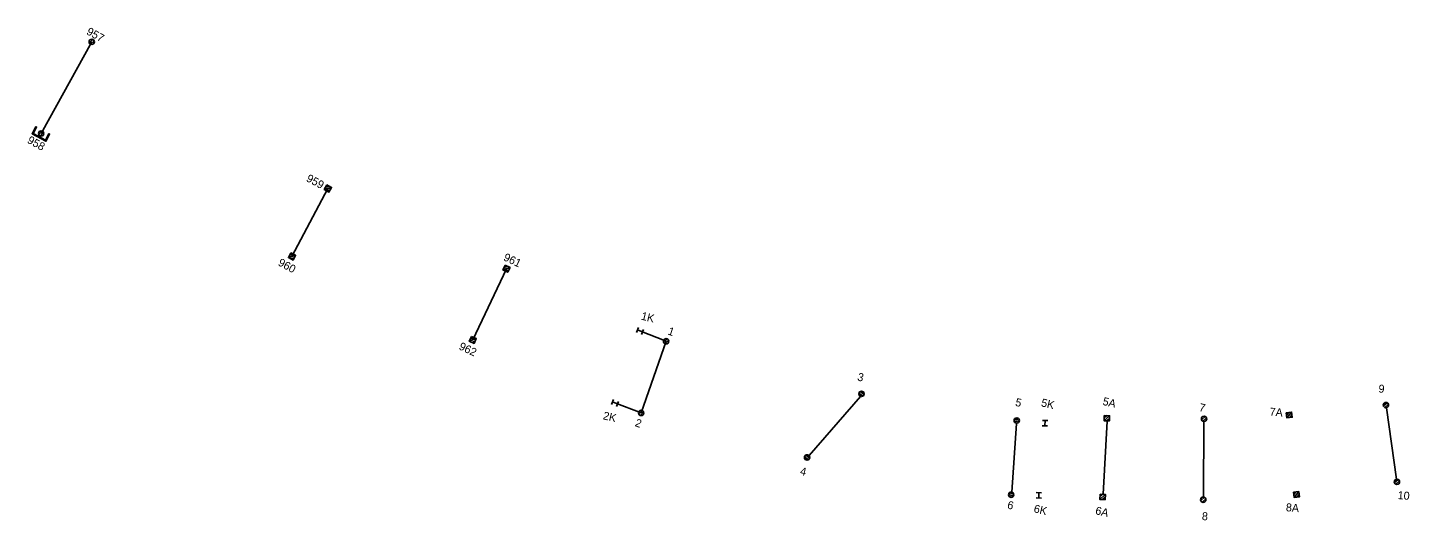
# Model space of a CAD drawing. Extents: x -595867 to -593796, y -1159595 to -1157495.
# Drawn here: x -594055.4 to -593796.4, y -1157836 to -1157743.6 of the extents above; entities that cross this region are included whole.
import ezdxf

# ---------------------------------------------------------------- set-up
doc = ezdxf.new("R2010")
doc.units = 0
doc.layers.add('BVK_kanalizace_jednotna_nova', color=7, linetype='Continuous')
doc.layers.add('Teplarny Horkovod', color=7, linetype='Continuous')

# ---------------------------------------------------------------- blocks, each defined once
blk = doc.blocks.new('C725')
at = {"layer": 'Teplarny Horkovod'}
for p, q in [((-0.46, -0.18), (0.18, 0.46)), ((-0.2, -0.45), (0.45, 0.2))]:
    blk.add_line(p, q, dxfattribs=at)
blk.add_circle((0, 0), 0.5, dxfattribs=at)
blk = doc.blocks.new('C661_3')
at = {"layer": 'Teplarny Horkovod'}
for p, q in [((-0.5, 0.03), (-0.03, 0.5)), ((-0.5, -0.5), (0.5, 0.5)), ((0.03, -0.5), (0.5, -0.03))]:
    blk.add_line(p, q, dxfattribs=at)
blk.add_lwpolyline([(-0.5, 0.5), (0.5, 0.5), (0.5, -0.5), (-0.5, -0.5)], close=True, dxfattribs=at)
blk.add_lwpolyline([(-0.5, 0.5), (0.5, 0.5), (0.5, -0.5), (-0.5, -0.5), (-0.5, 0.5)], dxfattribs=at)
blk = doc.blocks.new('C662')
at = {"layer": 'Teplarny Horkovod'}
for p, q in [((-0.5, 0.5), (0.5, 0.5)), ((0, 0.5), (0, -0.5)), ((-0.5, -0.5), (0.5, -0.5))]:
    blk.add_line(p, q, dxfattribs=at)

msp = doc.modelspace()

# ---------------------------------------------------------------- linework, layer by layer
at = {"layer": 'BVK_kanalizace_jednotna_nova'}
for p, q in [((-593899.56, -1157812.15), (-593898.82, -1157812.71)), ((-593899.33, -1157811.86), (-593898.6, -1157812.41)), ((-593801.25, -1157814.56), (-593800.57, -1157813.95)), ((-593801, -1157814.84), (-593800.32, -1157814.22)), ((-593853.62, -1157817.33), (-593852.58, -1157816.38)), ((-593853.6, -1157816.8), (-593853.11, -1157816.36)), ((-593835.35, -1157817.14), (-593834.67, -1157816.53)), ((-593835.1, -1157817.42), (-593834.42, -1157816.8)), ((-593819.41, -1157816.28), (-593819, -1157815.76)), ((-593819.34, -1157816.81), (-593818.48, -1157815.7)), ((-593818.82, -1157816.75), (-593818.41, -1157816.22)), ((-593870.48, -1157817.2), (-593869.59, -1157816.98)), ((-593870.4, -1157817.56), (-593869.5, -1157817.34)), ((-593865.2, -1157818.26), (-593864.2, -1157818.3)), ((-593865.16, -1157817.26), (-593864.16, -1157817.3)), ((-593864.66, -1157817.28), (-593864.7, -1157818.28)), ((-593853.1, -1157817.36), (-593852.6, -1157816.91)), ((-593909.76, -1157824.08), (-593909.02, -1157824.64)), ((-593909.53, -1157823.79), (-593908.8, -1157824.34)), ((-593799.18, -1157828.95), (-593798.5, -1157828.34)), ((-593798.93, -1157829.23), (-593798.25, -1157828.61)), ((-593871.52, -1157831.14), (-593870.63, -1157830.92)), ((-593871.44, -1157831.5), (-593870.54, -1157831.28)), ((-593866.36, -1157831.81), (-593865.36, -1157831.85)), ((-593866.32, -1157830.81), (-593865.32, -1157830.85)), ((-593865.82, -1157830.83), (-593865.86, -1157831.83)), ((-593854.42, -1157832.09), (-593853.38, -1157831.14)), ((-593854.39, -1157831.56), (-593853.9, -1157831.11)), ((-593853.89, -1157832.11), (-593853.4, -1157831.66)), ((-593835.5, -1157832.31), (-593834.82, -1157831.7)), ((-593835.25, -1157832.59), (-593834.57, -1157831.97)), ((-593818.05, -1157831.2), (-593817.65, -1157830.68)), ((-593817.99, -1157831.73), (-593817.12, -1157830.62)), ((-593817.46, -1157831.67), (-593817.05, -1157831.14))]:
    msp.add_line(p, q, dxfattribs=at)
for points in [[(-593908.89, -1157823.84), (-593899.3, -1157812.78)], [(-593853.58, -1157816.34), (-593852.58, -1157816.39), (-593852.62, -1157817.38), (-593853.62, -1157817.34), (-593853.58, -1157816.34)], [(-593819.47, -1157815.82), (-593818.47, -1157815.7), (-593818.35, -1157816.69), (-593819.34, -1157816.81), (-593819.47, -1157815.82)], [(-593798.77, -1157828.31), (-593800.66, -1157814.94)], [(-593870.91, -1157830.74), (-593870.01, -1157817.83)], [(-593853.78, -1157831.11), (-593853.04, -1157817.41)], [(-593834.98, -1157831.65), (-593834.91, -1157817.37)], [(-593854.37, -1157831.09), (-593853.37, -1157831.14), (-593853.42, -1157832.14), (-593854.42, -1157832.09), (-593854.37, -1157831.09)], [(-593818.11, -1157830.74), (-593817.12, -1157830.61), (-593816.99, -1157831.61), (-593817.99, -1157831.73), (-593818.11, -1157830.74)]]:
    msp.add_lwpolyline(points, dxfattribs=at)
for points in [[(-593853.58, -1157816.34), (-593852.58, -1157816.39), (-593852.62, -1157817.38), (-593853.62, -1157817.34)], [(-593819.47, -1157815.82), (-593818.47, -1157815.7), (-593818.35, -1157816.69), (-593819.34, -1157816.81)], [(-593854.37, -1157831.09), (-593853.37, -1157831.14), (-593853.42, -1157832.14), (-593854.42, -1157832.09)], [(-593818.11, -1157830.74), (-593817.12, -1157830.61), (-593816.99, -1157831.61), (-593817.99, -1157831.73)]]:
    msp.add_lwpolyline(points, close=True, dxfattribs=at)
for centre in [(-593899.08, -1157812.29), (-593899.08, -1157812.29), (-593800.78, -1157814.4), (-593800.78, -1157814.4), (-593869.99, -1157817.28), (-593869.99, -1157817.28), (-593834.88, -1157816.98), (-593834.88, -1157816.98), (-593909.28, -1157824.22), (-593909.28, -1157824.22), (-593798.71, -1157828.79), (-593798.71, -1157828.79), (-593871.03, -1157831.22), (-593871.03, -1157831.22), (-593835.03, -1157832.15), (-593835.03, -1157832.15)]:
    msp.add_circle(centre, 0.5, dxfattribs=at)
at = {"layer": 'Teplarny Horkovod'}
for p, q in [((-594043.38, -1157746.25), (-594052.86, -1157763.45)), ((-593999.1, -1157773.76), (-594005.85, -1157786.51)), ((-593965.62, -1157788.82), (-593971.95, -1157802.18)), ((-593935.71, -1157802.42), (-593940.62, -1157800.49)), ((-593935.71, -1157802.42), (-593940.39, -1157815.87)), ((-593940.39, -1157815.87), (-593945.31, -1157814))]:
    msp.add_line(p, q, dxfattribs=at)
msp.add_lwpolyline([(-594053.87, -1157762.16), (-594054.57, -1157763.49), (-594051.98, -1157764.9), (-594051.27, -1157763.57), (-594051.41, -1157763.49), (-594052.04, -1157764.68), (-594054.35, -1157763.42), (-594053.73, -1157762.23)], close=True, dxfattribs=at)

# ---------------------------------------------------------------- block references
for p in [(-594043.38, -1157746.25), (-594052.86, -1157763.45), (-593935.71, -1157802.42), (-593940.39, -1157815.87)]:
    msp.add_blockref('C725', p, dxfattribs=at)
for name, p, xscale, yscale, rotation in [('C661_3', (-593999.1, -1157773.76), 0.9999969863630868, 0.9999969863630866, -29.55893082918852), ('C661_3', (-594005.85, -1157786.51), 1.0000045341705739, 1.000004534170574, -26.973720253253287), ('C661_3', (-593965.62, -1157788.82), 1.0000010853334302, 1.00000108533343, -25.85007537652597), ('C662', (-593940.62, -1157800.49), 1.0000007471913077, 1.0000007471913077, 68.39513342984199), ('C661_3', (-593971.95, -1157802.18), 0.9999984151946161, 0.9999984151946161, -24.602231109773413), ('C662', (-593945.31, -1157814), 1.0000040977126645, 1.0000040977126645, 67.57843251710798)]:
    msp.add_blockref(name, p, dxfattribs=dict(at, xscale=xscale, yscale=yscale, rotation=rotation))

# ---------------------------------------------------------------- texts
at = {"layer": 'BVK_kanalizace_jednotna_nova'}
for s, rotation, p in [('1K', 346.76, (-593940.5, -1157798.35)), ('3', 346.76, (-593899.95, -1157809.76)), ('9', 355.6, (-593802.22, -1157812.03)), ('5', 346.76, (-593870.36, -1157814.51)), ('5K', 346.76, (-593865.52, -1157814.6)), ('5A', 346.76, (-593853.98, -1157814.34)), ('7', 346.76, (-593835.91, -1157815.49)), ('2K', 346.76, (-593947.64, -1157817.04)), ('7A', 355.6, (-593822.62, -1157816.37)), ('4', 346.76, (-593910.7, -1157827.45)), ('6', 346.76, (-593871.86, -1157833.78)), ('10', 355.6, (-593798.62, -1157832.02)), ('6K', 346.76, (-593866.9, -1157834.48)), ('6A', 346.76, (-593855.36, -1157834.83)), ('8', 355.6, (-593835.32, -1157835.95)), ('8A', 355.6, (-593819.57, -1157834.3))]:
    msp.add_text(s, height=1.5, rotation=rotation, dxfattribs=at).set_placement(p)
at = {"layer": 'Teplarny Horkovod'}
for s, rotation, p in [('957', 331.0143, (-594044.5, -1157744.75)), ('958', 331.0143, (-594055.6, -1157765.12)), ('959', 331.4815, (-594003.3, -1157772.31)), ('960', 331.4815, (-594008.6, -1157788.1)), ('961', 334.5373, (-593966.34, -1157787.17)), ('1', 340.8475, (-593935.51, -1157801.11)), ('962', 334.5373, (-593974.69, -1157803.87)), ('2', 340.8475, (-593941.67, -1157818.31))]:
    msp.add_text(s, height=1.5, rotation=rotation, dxfattribs=at).set_placement(p)

doc.saveas('drawing.dxf')
